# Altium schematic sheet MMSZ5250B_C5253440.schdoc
size 127 x 101 mm
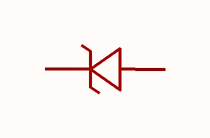
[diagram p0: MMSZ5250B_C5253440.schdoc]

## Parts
D?  mmsz5250b_c5253440  [SOD-123_L3.1-W1.7-LS3.7-RD-1]  (value not drawn)

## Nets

Not connected (* = marked no-connect by the designer): D? 1(K) 2(A)

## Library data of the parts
D? = mmsz5250b_c5253440: 二极管配置:1个独立式;稳压值(标称值):20V;稳压值(范围):19V~21V;耗散功率(Pd):500mW;; Manufacturer: MDD(辰达半导体); AddInBom: yes; ModelId: e64708ca597044b4b98d2b6eaba3c9bd; ModelTransform: 145.669,67.008,0,0,0,0,0,-0.394,0; Diode Configuration: 1个独立式; Zener Voltage(Nom): 20V; Reverse Leakage Current (Ir): 100nA@15V; Pd - Power Dissipation: 500mW; Impedance(Zzt): 25Ω; Impedance(Zzk): 600Ω; Tolerance: ±5%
